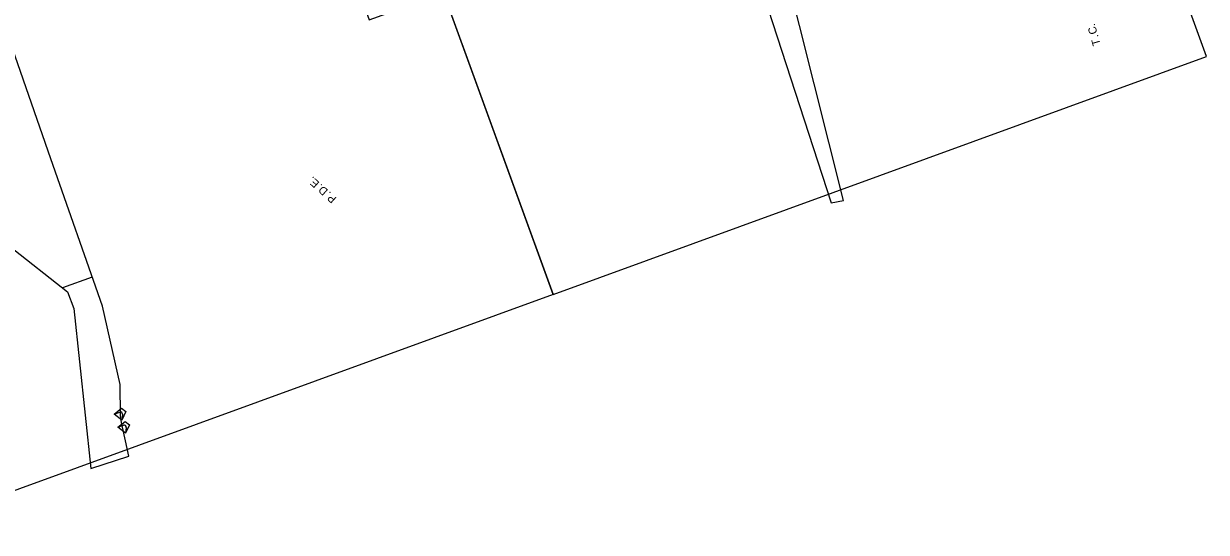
# Model space of a CAD drawing. Extents: x 960650 to 962115, y 1906901 to 1908757.
# Drawn here: x 961228 to 962115, y 1906901 to 1907282 of the extents above; entities that cross this region are included whole.
import ezdxf

# ---------------------------------------------------------------- set-up
doc = ezdxf.new("R2010")
doc.units = 0
for name, color, linetype in [('1', 7, 'Continuous'), ('DRAINAGE STRUCTURES', 7, 'Continuous'), ('NO PLOT', 7, 'Continuous'), ('R_Draft', 7, 'Continuous'), ('R_Horz Alg Annot', 7, 'Continuous')]:
    doc.layers.add(name, color=color, linetype=linetype)

msp = doc.modelspace()

# ---------------------------------------------------------------- linework, layer by layer
at = {"layer": '1'}
msp.add_line((961624.82, 1907079.46), (961542.56, 1907305.48), dxfattribs=at)
at = {"layer": 'DRAINAGE STRUCTURES'}
for p, q in [((961295.63, 1906989.76), (961299.75, 1906991.3)), ((961301.36, 1906985.34), (961295.63, 1906989.76)), ((961301.81, 1906989.71), (961301.36, 1906985.34)), ((961298.41, 1906979.88), (961302.52, 1906981.42)), ((961304.13, 1906975.46), (961298.41, 1906979.88)), ((961304.58, 1906979.83), (961304.13, 1906975.46))]:
    msp.add_line(p, q, dxfattribs=at)
for points in [[(961295.63, 1906989.76), (961301.05, 1906994.19), (961304.28, 1906991.7), (961301.36, 1906985.34)], [(961298.41, 1906979.88), (961303.83, 1906984.31), (961307.06, 1906981.82), (961304.13, 1906975.46)]]:
    msp.add_lwpolyline(points, close=True, dxfattribs=at)
for centre in [(961300.29, 1906989.86), (961303.06, 1906979.98)]:
    msp.add_arc(centre, 1.53, 354.13577, 110.42269, dxfattribs=at)
at = {"layer": 'NO PLOT'}
for points in [[(962114.55, 1907257.7), (961568.91, 1908756.85), (961079.18, 1908578.6), (961182.12, 1908295.76), (961245.55, 1908318.85), (961390.91, 1907919.48), (961327.48, 1907896.39), (961425.36, 1907627.47), (961483.4, 1907648.6), (961600.59, 1907326.6), (961542.56, 1907305.48), (961624.82, 1907079.46)], [(962114.55, 1907257.7), (961568.91, 1908756.85), (961079.18, 1908578.6), (961182.12, 1908295.76), (961245.55, 1908318.85), (961390.91, 1907919.48), (961327.48, 1907896.39), (961425.36, 1907627.47), (961483.4, 1907648.6), (961600.59, 1907326.6), (961542.56, 1907305.48), (961624.82, 1907079.46)], [(962114.55, 1907257.7), (961568.91, 1908756.85), (961079.18, 1908578.6), (961182.12, 1908295.76), (961245.55, 1908318.85), (961390.91, 1907919.48), (961327.48, 1907896.39), (961425.36, 1907627.47), (961483.4, 1907648.6), (961600.59, 1907326.6), (961542.56, 1907305.48), (961624.82, 1907079.46)], [(962114.55, 1907257.7), (961568.91, 1908756.85), (961079.18, 1908578.6), (961182.12, 1908295.76), (961245.55, 1908318.85), (961390.91, 1907919.48), (961327.48, 1907896.39), (961425.36, 1907627.47), (961483.4, 1907648.6), (961600.59, 1907326.6), (961542.56, 1907305.48), (961624.82, 1907079.46)], [(961135.09, 1906901.21), (960730.12, 1908013.86), (960776.54, 1908030.76), (960709.57, 1908214.75), (960723.29, 1908219.74), (960649.59, 1908422.25), (961079.18, 1908578.6), (961182.12, 1908295.76), (961109.77, 1908269.43), (961255.13, 1907870.06), (961327.48, 1907896.39), (961425.36, 1907627.47), (961369.64, 1907607.19), (961486.84, 1907285.2), (961542.56, 1907305.48), (961624.82, 1907079.46)], [(961135.09, 1906901.21), (960730.12, 1908013.86), (960776.54, 1908030.76), (960709.57, 1908214.75), (960723.29, 1908219.74), (960649.59, 1908422.25), (961079.18, 1908578.6), (961182.12, 1908295.76), (961109.77, 1908269.43), (961255.13, 1907870.06), (961327.48, 1907896.39), (961425.36, 1907627.47), (961369.64, 1907607.19), (961486.84, 1907285.2), (961542.56, 1907305.48), (961624.82, 1907079.46)], [(961135.09, 1906901.21), (960730.12, 1908013.86), (960776.54, 1908030.76), (960709.57, 1908214.75), (960723.29, 1908219.74), (960649.59, 1908422.25), (961079.18, 1908578.6), (961182.12, 1908295.76), (961109.77, 1908269.43), (961255.13, 1907870.06), (961327.48, 1907896.39), (961425.36, 1907627.47), (961369.64, 1907607.19), (961486.84, 1907285.2), (961542.56, 1907305.48), (961624.82, 1907079.46)], [(961135.09, 1906901.21), (960730.12, 1908013.86), (960776.54, 1908030.76), (960709.57, 1908214.75), (960723.29, 1908219.74), (960649.59, 1908422.25), (961079.18, 1908578.6), (961182.12, 1908295.76), (961109.77, 1908269.43), (961255.13, 1907870.06), (961327.48, 1907896.39), (961425.36, 1907627.47), (961369.64, 1907607.19), (961486.84, 1907285.2), (961542.56, 1907305.48), (961624.82, 1907079.46)]]:
    msp.add_lwpolyline(points, close=True, dxfattribs=at)
for points in [[(961546.11, 1908053.77), (961660.88, 1907856.14), (961665.4, 1907852.91), (961665.4, 1907852.91), (961672.08, 1907797.08), (961685.77, 1907691.1), (961721.87, 1907490.67), (961833.17, 1907148.06), (961842.49, 1907149.72), (961765.53, 1907456.14), (961778.4, 1907476.17), (961766.21, 1907525.48), (961699.17, 1907713.63), (961665.82, 1907852.62), (961665.4, 1907852.91), (961665.4, 1907852.91), (961665.39, 1907852.96), (961665.26, 1907853.71), (961666.04, 1907863.2), (961658.05, 1907894.81)], [(960955.08, 1907916.13), (961008.1, 1907767.13), (961018.52, 1907704.78), (961110.98, 1907455.73), (961216.96, 1907180.04), (961204.28, 1907151.3), (961216.79, 1907115.84), (961260.7, 1907081.39), (961265.37, 1907068.97), (961278.06, 1906949.14), (961306.7, 1906958.35), (961300.99, 1906983.42), (961300.43, 1906988.85), (961300.21, 1907012.09), (961286.79, 1907070.54), (961248.21, 1907180.96), (961138.72, 1907495.58), (961092.52, 1907629.16), (961034.31, 1907757.57), (961052.3, 1907780), (961046.81, 1907795.09), (961017.22, 1907805.64), (960993.47, 1907918.44)]]:
    msp.add_lwpolyline(points, dxfattribs=at)
at = {"layer": 'R_Horz Alg Annot'}
msp.add_lwpolyline([(961279.19, 1907092.28), (961256.88, 1907084.39)], dxfattribs=at)

# ---------------------------------------------------------------- texts
at = {"layer": 'R_Draft'}
for s, rotation, p in [('C', 105.81657, (962032.94, 1907275.23)), ('.', 105.81657, (962031.4, 1907280.68)), ('.', 105.81657, (962033.74, 1907272.41)), ('T', 105.81657, (962035.34, 1907266.78)), ('E', 138.10209, (961449.96, 1907163.2)), ('.', 138.10209, (961445.95, 1907166.79)), ('D', 138.10209, (961456.36, 1907157.45)), ('.', 138.10209, (961452.14, 1907161.24)), ('.', 138.10209, (961458.54, 1907155.5)), ('P', 138.10209, (961462.76, 1907151.71))]:
    msp.add_text(s, height=6, rotation=rotation, dxfattribs=at).set_placement(p)

doc.saveas('drawing.dxf')
